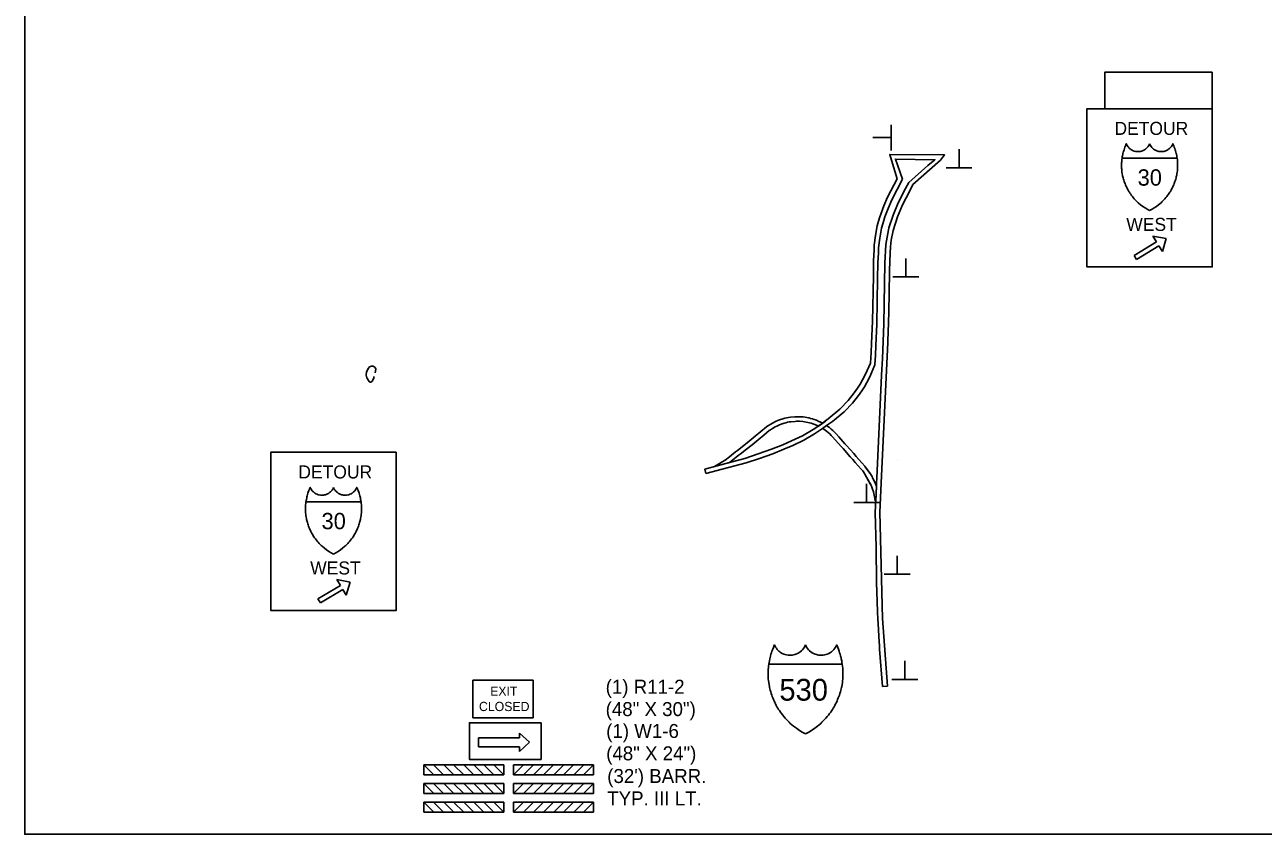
# Model space of a CAD drawing. Extents: x 759117 to 1215197, y 961017 to 2072683.
# Drawn here: x 759117 to 838885, y 961017 to 1013133 of the extents above; entities that cross this region are included whole.
import ezdxf

# ---------------------------------------------------------------- set-up
doc = ezdxf.new("R2010")
doc.units = 0
for name, color, linetype in [('23', 7, 'Continuous'), ('DETOUR', 7, 'Continuous'), ('G-ANNO-TEXT', 7, 'Continuous'), ('Level 19', 7, 'Continuous'), ('Level 3', 7, 'Continuous'), ('Level 35', 7, 'Continuous'), ('Level 8', 7, 'Continuous'), ('NO PLOT CELL', 7, 'Continuous')]:
    doc.layers.add(name, color=color, linetype=linetype)

msp = doc.modelspace()

# ---------------------------------------------------------------- linework, layer by layer
at = {"layer": '23'}
for points in [[(829792, 1004536), (829805, 1004620), (829819, 1004695), (829839, 1004792), (829853, 1004855), (829872, 1004930), (829897, 1005018), (829920, 1005091), (829945, 1005167), (829979, 1005260), (830014, 1005348), (830043, 1005415), (830067, 1005469), (830093, 1005411), (830123, 1005356), (830156, 1005306), (830199, 1005250), (830233, 1005212), (830276, 1005171), (830318, 1005136), (830365, 1005102), (830438, 1005058), (830514, 1005023), (830582, 1004999), (830650, 1004981), (830722, 1004969), (830806, 1004964), (830862, 1004965), (830925, 1004971), (830982, 1004980), (831042, 1004995), (831103, 1005015), (831186, 1005051), (831242, 1005083), (831308, 1005128), (831371, 1005181), (831417, 1005228), (831470, 1005292), (831513, 1005357), (831538, 1005402), (831566, 1005462)], [(831566, 1005462), (831594, 1005402), (831620, 1005357), (831663, 1005292), (831716, 1005228), (831762, 1005181), (831825, 1005128), (831891, 1005083), (831947, 1005051), (832029, 1005015), (832091, 1004995), (832151, 1004980), (832208, 1004971), (832271, 1004965), (832327, 1004964), (832411, 1004969), (832483, 1004981), (832551, 1004999), (832619, 1005023), (832695, 1005058), (832768, 1005102), (832815, 1005136), (832857, 1005171), (832900, 1005212), (832934, 1005250), (832977, 1005306), (833010, 1005356), (833040, 1005411), (833066, 1005469), (833090, 1005415), (833119, 1005348), (833154, 1005260), (833188, 1005167), (833213, 1005091), (833236, 1005018), (833261, 1004930), (833280, 1004855), (833294, 1004792), (833314, 1004695), (833328, 1004620), (833341, 1004536)], [(831566, 1001175), (831411, 1001257), (831274, 1001340), (831124, 1001441), (830983, 1001548), (830830, 1001679), (830772, 1001732), (830707, 1001796), (830647, 1001858), (830581, 1001931), (830516, 1002006), (830462, 1002073), (830403, 1002149), (830350, 1002223), (830303, 1002291), (830263, 1002353), (830229, 1002408), (830185, 1002483), (830150, 1002545), (830112, 1002618), (830075, 1002693), (830043, 1002762), (830014, 1002829), (829984, 1002904), (829957, 1002974), (829931, 1003047), (829907, 1003123), (829883, 1003200), (829863, 1003275), (829845, 1003345), (829831, 1003408), (829821, 1003455), (829804, 1003545), (829788, 1003649), (829777, 1003736), (829769, 1003828), (829764, 1003902), (829761, 1003996), (829760, 1004084), (829762, 1004181), (829765, 1004245), (829768, 1004304), (829771, 1004341), (829780, 1004437), (829792, 1004536)], [(833341, 1004536), (829792, 1004536)], [(829792, 1004536), (833341, 1004536)], [(833341, 1004536), (833353, 1004437), (833362, 1004341), (833365, 1004304), (833368, 1004245), (833371, 1004181), (833373, 1004084), (833372, 1003996), (833368, 1003902), (833364, 1003828), (833356, 1003736), (833345, 1003649), (833329, 1003545), (833312, 1003455), (833302, 1003408), (833288, 1003345), (833270, 1003275), (833250, 1003200), (833226, 1003123), (833201, 1003047), (833176, 1002974), (833149, 1002904), (833119, 1002829), (833090, 1002762), (833057, 1002693), (833020, 1002618), (832982, 1002545), (832948, 1002483), (832904, 1002408), (832870, 1002353), (832829, 1002291), (832783, 1002223), (832730, 1002149), (832671, 1002073), (832617, 1002006), (832552, 1001931), (832486, 1001858), (832426, 1001796), (832361, 1001732), (832303, 1001679), (832150, 1001548), (832009, 1001441), (831859, 1001340), (831722, 1001257), (831566, 1001175)], [(777229, 982416), (777242, 982501), (777255, 982576), (777275, 982672), (777290, 982735), (777309, 982810), (777333, 982898), (777356, 982972), (777381, 983047), (777415, 983141), (777450, 983228), (777479, 983296), (777503, 983349), (777529, 983292), (777560, 983237), (777593, 983186), (777636, 983130), (777670, 983093), (777712, 983052), (777755, 983016), (777801, 982982), (777875, 982938), (777950, 982903), (778019, 982879), (778086, 982861), (778159, 982849), (778243, 982844), (778298, 982845), (778362, 982851), (778418, 982861), (778479, 982875), (778540, 982896), (778622, 982932), (778679, 982964), (778745, 983009), (778808, 983062), (778854, 983108), (778906, 983172), (778950, 983237), (778975, 983282), (779003, 983342)], [(779003, 983342), (779031, 983282), (779056, 983237), (779100, 983172), (779152, 983108), (779198, 983062), (779262, 983009), (779327, 982964), (779384, 982932), (779466, 982896), (779527, 982875), (779588, 982861), (779644, 982851), (779708, 982845), (779763, 982844), (779847, 982849), (779920, 982861), (779987, 982879), (780056, 982903), (780131, 982938), (780205, 982982), (780251, 983016), (780294, 983052), (780336, 983093), (780370, 983130), (780413, 983186), (780447, 983237), (780477, 983292), (780503, 983349), (780527, 983296), (780556, 983228), (780591, 983141), (780625, 983047), (780650, 982972), (780673, 982898), (780697, 982810), (780716, 982735), (780731, 982672), (780751, 982576), (780764, 982501), (780777, 982416)], [(779003, 979055), (778848, 979138), (778711, 979220), (778560, 979322), (778420, 979428), (778266, 979559), (778209, 979612), (778144, 979676), (778083, 979738), (778017, 979811), (777952, 979886), (777898, 979953), (777840, 980030), (777786, 980103), (777740, 980171), (777699, 980234), (777666, 980288), (777621, 980364), (777587, 980426), (777549, 980498), (777512, 980573), (777480, 980643), (777451, 980710), (777420, 980785), (777394, 980854), (777368, 980927), (777343, 981003), (777320, 981081), (777300, 981155), (777282, 981225), (777268, 981288), (777258, 981335), (777241, 981425), (777225, 981530), (777214, 981616), (777206, 981708), (777201, 981782), (777198, 981876), (777197, 981964), (777198, 982062), (777201, 982126), (777205, 982185), (777207, 982222), (777217, 982318), (777229, 982416)], [(780777, 982416), (777229, 982416)], [(777229, 982416), (780777, 982416)], [(780777, 982416), (780789, 982318), (780799, 982222), (780801, 982185), (780805, 982126), (780808, 982062), (780809, 981964), (780809, 981876), (780805, 981782), (780800, 981708), (780792, 981616), (780781, 981530), (780765, 981425), (780748, 981335), (780738, 981288), (780724, 981225), (780707, 981155), (780686, 981081), (780663, 981003), (780638, 980927), (780612, 980854), (780586, 980785), (780555, 980710), (780526, 980643), (780494, 980573), (780457, 980498), (780419, 980426), (780385, 980364), (780340, 980288), (780307, 980234), (780266, 980171), (780220, 980103), (780166, 980030), (780108, 979953), (780054, 979886), (779989, 979811), (779923, 979738), (779862, 979676), (779797, 979612), (779740, 979559), (779586, 979428), (779446, 979322), (779295, 979220), (779158, 979138), (779003, 979055)], [(807040, 971965), (807058, 972078), (807075, 972178), (807102, 972307), (807121, 972391), (807147, 972491), (807180, 972608), (807210, 972706), (807244, 972807), (807289, 972931), (807335, 973048), (807374, 973138), (807406, 973210), (807441, 973133), (807481, 973059), (807525, 972992), (807583, 972918), (807628, 972868), (807685, 972813), (807742, 972765), (807803, 972720), (807901, 972662), (808002, 972615), (808093, 972582), (808183, 972559), (808280, 972543), (808392, 972536), (808466, 972537), (808551, 972545), (808626, 972558), (808707, 972578), (808788, 972605), (808898, 972653), (808973, 972695), (809061, 972755), (809145, 972826), (809207, 972888), (809277, 972973), (809335, 973060), (809369, 973121), (809406, 973201)], [(809406, 973201), (809443, 973121), (809477, 973060), (809535, 972973), (809605, 972888), (809666, 972826), (809751, 972755), (809838, 972695), (809914, 972653), (810023, 972605), (810105, 972578), (810185, 972558), (810261, 972545), (810346, 972537), (810419, 972536), (810532, 972543), (810628, 972559), (810718, 972582), (810809, 972615), (810910, 972662), (811008, 972720), (811070, 972765), (811127, 972813), (811183, 972868), (811229, 972918), (811286, 972992), (811330, 973059), (811371, 973133), (811406, 973210), (811438, 973138), (811476, 973048), (811523, 972931), (811568, 972807), (811602, 972706), (811632, 972608), (811665, 972491), (811690, 972391), (811710, 972307), (811736, 972178), (811754, 972078), (811771, 971965)], [(809406, 967484), (809199, 967594), (809016, 967704), (808816, 967840), (808628, 967981), (808424, 968156), (808347, 968227), (808260, 968312), (808180, 968395), (808092, 968492), (808005, 968592), (807933, 968681), (807855, 968783), (807783, 968882), (807722, 968972), (807668, 969056), (807623, 969128), (807564, 969229), (807518, 969312), (807467, 969408), (807418, 969508), (807375, 969601), (807336, 969690), (807295, 969790), (807260, 969883), (807226, 969980), (807193, 970081), (807162, 970185), (807134, 970284), (807111, 970378), (807092, 970462), (807079, 970524), (807056, 970644), (807035, 970784), (807020, 970899), (807009, 971021), (807003, 971120), (806999, 971246), (806997, 971363), (807000, 971493), (807003, 971578), (807008, 971657), (807012, 971706), (807024, 971834), (807040, 971965)], [(811771, 971965), (807040, 971965)], [(807040, 971965), (811771, 971965)], [(811771, 971965), (811788, 971834), (811800, 971706), (811804, 971657), (811808, 971578), (811812, 971493), (811814, 971363), (811813, 971246), (811808, 971120), (811802, 971021), (811792, 970899), (811777, 970784), (811755, 970644), (811733, 970524), (811720, 970462), (811701, 970378), (811677, 970284), (811650, 970185), (811619, 970081), (811586, 969980), (811552, 969883), (811516, 969790), (811475, 969690), (811437, 969601), (811394, 969508), (811345, 969408), (811294, 969312), (811248, 969229), (811189, 969128), (811144, 969056), (811090, 968972), (811028, 968882), (810957, 968783), (810879, 968681), (810807, 968592), (810720, 968492), (810632, 968395), (810551, 968312), (810465, 968227), (810388, 968156), (810183, 967981), (809996, 967840), (809795, 967704), (809613, 967594), (809406, 967484)]]:
    msp.add_lwpolyline(points, dxfattribs=at)
at = {"layer": 'DETOUR'}
for p, q in [((814928, 1005035), (814928, 1006698)), ((814928, 1005866), (813731, 1005866)), ((819293, 1003919), (819293, 1005116)), ((818090, 1004417), (816323, 1002843)), ((816323, 1002843), (818090, 1004417)), ((818461, 1003919), (820124, 1003919)), ((832011, 999160), (830565, 998284)), ((832167, 998903), (830720, 998028)), ((815867, 996896), (815867, 998093)), ((830565, 998284), (830720, 998028)), ((815035, 996896), (816698, 996896)), ((802911, 984531), (802987, 984243)), ((802911, 984531), (802987, 984243)), ((813343, 982375), (813343, 983573)), ((812511, 982375), (814174, 982375)), ((815307, 977752), (815307, 978949)), ((814476, 977752), (816139, 977752)), ((779448, 977040), (778001, 976165)), ((779603, 976784), (778157, 975908)), ((778001, 976165), (778157, 975908)), ((815798, 970984), (815798, 972181)), ((814966, 970984), (816629, 970984)), ((814369, 970526), (814690, 970556)), ((814369, 970526), (814690, 970556))]:
    msp.add_line(p, q, dxfattribs=at)
for points in [[(818090, 1004417), (818361, 1004756), (814825, 1004788), (814949, 1004413), (815312, 1003208)], [(818090, 1004417), (818361, 1004756), (814825, 1004788), (814949, 1004413), (815312, 1003208)], [(817288, 1004068), (817738, 1004441), (815197, 1004489), (815657, 1003193)], [(815657, 1003193), (815197, 1004489), (817738, 1004441), (817288, 1004068)], [(813897, 981735), (813974, 983412), (813984, 983643), (813999, 983951), (814304, 990583), (814353, 991642), (814447, 993849), (814514, 997780), (814585, 998978), (814752, 999937), (814778, 1000054), (815044, 1000878), (815382, 1001668), (815854, 1002588), (816060, 1002981), (817288, 1004068)], [(817288, 1004068), (816060, 1002981), (815854, 1002588), (815382, 1001668), (815044, 1000878), (814778, 1000054), (814752, 999937), (814585, 998978), (814514, 997780), (814447, 993849), (814353, 991642), (814304, 990583), (813999, 983951), (813984, 983643), (813974, 983412), (813897, 981735)], [(815312, 1003208), (814694, 1002030), (814446, 1001467), (814245, 1000944), (814166, 1000703), (814029, 1000196), (813906, 999555), (813833, 998947), (813820, 998625), (813782, 997961), (813774, 996951), (813715, 994026), (813658, 992643), (813630, 992034), (813586, 991344), (813269, 990642), (813080, 990269), (812918, 989985), (812757, 989732), (812545, 989426), (812152, 988941), (811988, 988760), (811813, 988580), (811613, 988384), (810862, 987760), (810489, 987489)], [(815312, 1003208), (814694, 1002030), (814446, 1001467), (814245, 1000944), (814166, 1000703), (814029, 1000196), (813906, 999555), (813833, 998947), (813820, 998625), (813782, 997961), (813774, 996951), (813715, 994026), (813658, 992643), (813630, 992034), (813586, 991344), (813269, 990642), (813080, 990269), (812918, 989985), (812757, 989732), (812545, 989426), (812152, 988941), (811988, 988760), (811813, 988580), (811613, 988384), (810862, 987760), (810678, 987627)], [(815657, 1003193), (814971, 1001864), (814723, 1001301), (814523, 1000778), (814443, 1000537), (814306, 1000030), (814184, 999389), (814111, 998781), (814097, 998459), (814060, 997795), (814051, 996785), (813993, 993860), (813936, 992477), (813908, 991867), (813878, 991229), (813546, 990476), (813358, 990103), (813195, 989819), (813034, 989566), (812822, 989260), (812429, 988775), (812265, 988594), (812091, 988414), (811891, 988218), (811139, 987594), (810766, 987323)], [(810766, 987323), (811139, 987594), (811891, 988218), (812091, 988414), (812265, 988594), (812429, 988775), (812822, 989260), (813034, 989566), (813195, 989819), (813358, 990103), (813546, 990476), (813878, 991229), (813908, 991867), (813936, 992477), (813993, 993860), (814051, 996785), (814060, 997795), (814097, 998459), (814111, 998781), (814184, 999389), (814306, 1000030), (814443, 1000537), (814523, 1000778), (814723, 1001301), (814971, 1001864), (815657, 1003193)], [(816323, 1002843), (816119, 1002451), (815651, 1001540), (815322, 1000772), (815043, 999877), (814927, 999273), (814869, 998834), (814849, 998422), (814806, 997331), (814783, 995757), (814764, 994771), (814745, 993841), (814734, 993460), (814698, 992684), (814677, 992230), (814302, 984091), (814194, 981742)], [(814194, 981742), (814302, 984091), (814677, 992230), (814698, 992684), (814734, 993460), (814745, 993841), (814764, 994771), (814783, 995757), (814806, 997331), (814849, 998422), (814869, 998834), (814927, 999273), (815043, 999877), (815322, 1000772), (815651, 1001540), (816119, 1002451), (816323, 1002843)], [(810690, 987610), (810431, 987422), (809906, 987074), (809217, 986668), (808504, 986343), (807939, 986088), (807212, 985802), (806364, 985498), (805501, 985211), (803958, 984808), (802911, 984531)], [(810606, 987574), (810489, 987489), (810229, 987288)], [(810678, 987627), (810606, 987574)], [(810229, 987288), (809906, 987074), (809217, 986668), (808504, 986343), (807939, 986088), (807212, 985802), (806364, 985498), (805501, 985211), (803958, 984808), (802911, 984531)], [(810766, 987323), (810507, 987134), (809982, 986786), (809293, 986380), (808580, 986055), (808015, 985800), (807289, 985515), (806440, 985210), (805577, 984923), (804034, 984521), (802987, 984243)], [(802987, 984243), (804034, 984521), (805577, 984923), (806440, 985210), (807289, 985515), (808015, 985800), (808580, 986055), (809293, 986380), (809982, 986786), (810507, 987134), (810766, 987323)], [(814369, 970526), (814176, 972939), (814161, 973153), (814130, 973726), (814109, 974221), (814068, 974890), (814047, 975305), (814027, 976017), (813977, 977197), (813950, 979491), (813897, 981735)], [(813897, 981735), (813950, 979491), (813977, 977197), (814027, 976017), (814047, 975305), (814068, 974890), (814109, 974221), (814130, 973726), (814161, 973153), (814176, 972939), (814369, 970526)], [(814194, 981742), (814365, 974907), (814690, 970556)], [(814690, 970556), (814365, 974907), (814194, 981742)]]:
    msp.add_lwpolyline(points, dxfattribs=at)
at = {"layer": 'Level 19'}
for p, q in [((810435, 987519), (810270, 987599)), ((810146, 987328), (810229, 987288)), ((810229, 987288), (810431, 987422)), ((810431, 987422), (810500, 987472)), ((810505, 987480), (810435, 987519)), ((810766, 987323), (810507, 987134)), ((813248, 984676), (813218, 984712)), ((813248, 984676), (813587, 984216)), ((813234, 984209), (813614, 983507)), ((813234, 984209), (813577, 983575)), ((813723, 983971), (813904, 983587)), ((813974, 983412), (813904, 983587)), ((813931, 982480), (813974, 983412))]:
    msp.add_line(p, q, dxfattribs=at)
for points in [[(810270, 987599), (810108, 987669), (809966, 987722), (809851, 987759), (809734, 987792), (809617, 987821), (809498, 987846), (809379, 987866), (809258, 987881), (809033, 987899), (808925, 987901), (808818, 987900), (808711, 987896), (808432, 987871), (808309, 987852), (808189, 987828), (808070, 987800), (807951, 987767), (807731, 987693), (807625, 987651), (807521, 987607), (807419, 987558), (807319, 987506), (807138, 987405), (807053, 987353), (806975, 987302), (806887, 987238), (806524, 986941), (806160, 986637), (805773, 986318), (805424, 986035), (805016, 985720), (804889, 985629), (804508, 985325), (804233, 985110), (804084, 985009), (803541, 984698)], [(804502, 984950), (804692, 985092), (805068, 985392), (805193, 985481), (805609, 985801), (805962, 986088), (806350, 986408), (806713, 986712), (807069, 987002), (807145, 987057), (807213, 987102), (807288, 987148), (807460, 987244), (807551, 987292), (807644, 987335), (807738, 987376), (807833, 987413), (808038, 987482), (808144, 987512), (808252, 987537), (808360, 987559), (808468, 987575), (808730, 987599), (808826, 987603), (808923, 987604), (809018, 987602), (809227, 987585), (809335, 987571), (809443, 987553), (809551, 987531), (809658, 987505), (809764, 987475), (809868, 987441), (809997, 987393), (810146, 987328)], [(810500, 987472), (810505, 987480)], [(810507, 987134), (810584, 987087), (810674, 987026), (810761, 986963), (810862, 986878), (810962, 986787), (811058, 986695), (811153, 986599), (811322, 986407)], [(811544, 986605), (811371, 986802), (811267, 986907), (811165, 987005), (811057, 987102), (810945, 987197), (810845, 987269), (810766, 987323)], [(811322, 986407), (811727, 985956), (811829, 985845), (812286, 985321), (812454, 985136), (812612, 984951), (812993, 984516)], [(813218, 984712), (812837, 985146), (812677, 985333), (812508, 985519), (812051, 986045), (811946, 986156), (811544, 986605)], [(803541, 984698), (803958, 984808), (804502, 984950)], [(804502, 984950), (804502, 984950)], [(812993, 984516), (813086, 984409), (813130, 984354), (813212, 984242)], [(813587, 984216), (813555, 984260), (813248, 984676)], [(813212, 984242), (813234, 984209)], [(813577, 983575), (813582, 983578)], [(813582, 983578), (813614, 983507), (813646, 983437)], [(813723, 983971), (813689, 984040), (813616, 984169), (813587, 984216)], [(813904, 983587), (813888, 983623), (813756, 983902), (813723, 983971)], [(813646, 983437), (813723, 983234), (813781, 983054), (813833, 982850), (813858, 982731), (813897, 982482)], [(813897, 982482), (813931, 982480)]]:
    msp.add_lwpolyline(points, dxfattribs=at)
at = {"layer": 'Level 3'}
for p, q in [((815349, 985063), (815346, 985066)), ((787978, 968507), (787978, 970939)), ((787978, 970939), (791870, 970939)), ((791870, 968507), (791870, 970939)), ((787978, 968507), (791870, 968507)), ((788349, 966641), (788349, 967228)), ((789980, 965490), (784817, 965490)), ((784817, 964842), (784817, 965490)), ((789980, 964844), (789980, 965490)), ((790590, 964844), (790590, 965490)), ((790590, 965490), (795753, 965490)), ((795753, 964842), (795753, 965490)), ((789980, 964830), (784817, 964830)), ((790590, 964830), (795753, 964830)), ((789980, 964288), (784817, 964288)), ((784817, 963642), (784817, 964288)), ((789980, 963642), (784817, 963642)), ((789980, 963642), (789980, 964288)), ((790590, 964288), (795753, 964288)), ((790590, 963642), (790590, 964288)), ((790590, 963642), (795753, 963642)), ((795753, 963642), (795753, 964288)), ((784817, 962444), (784817, 963091)), ((789980, 963091), (784817, 963091)), ((789980, 962444), (789980, 963091)), ((790590, 963091), (795753, 963091)), ((790590, 962444), (790590, 963091)), ((795753, 962444), (795753, 963091)), ((789980, 962431), (784817, 962431)), ((790590, 962431), (795753, 962431))]:
    msp.add_line(p, q, dxfattribs=at)
for points in [[(784817, 965490), (785452, 965488), (786097, 964844), (785464, 964844)], [(786107, 965490), (786742, 965488), (787387, 964844), (786754, 964844)], [(787397, 965490), (788032, 965488), (788677, 964844), (788044, 964844)], [(788687, 965490), (789322, 965488), (789967, 964844), (789334, 964844)], [(791883, 965490), (791248, 965488), (790604, 964844), (791237, 964844)], [(793173, 965490), (792538, 965488), (791894, 964844), (792527, 964844)], [(794463, 965490), (793828, 965488), (793184, 964844), (793817, 964844)], [(795753, 965490), (795118, 965488), (794474, 964844), (795107, 964844)], [(784817, 964288), (785452, 964286), (786097, 963642), (785464, 963642)], [(786107, 964288), (786742, 964286), (787387, 963642), (786754, 963642)], [(787397, 964288), (788032, 964286), (788677, 963642), (788044, 963642)], [(788687, 964288), (789322, 964286), (789967, 963642), (789334, 963642)], [(791883, 964288), (791248, 964286), (790604, 963642), (791237, 963642)], [(793173, 964288), (792538, 964286), (791894, 963642), (792527, 963642)], [(794463, 964288), (793828, 964286), (793184, 963642), (793817, 963642)], [(795753, 964288), (795118, 964286), (794474, 963642), (795107, 963642)], [(784817, 963091), (785452, 963089), (786097, 962444), (785464, 962444)], [(786107, 963091), (786742, 963089), (787387, 962444), (786754, 962444)], [(787397, 963091), (788032, 963089), (788677, 962444), (788044, 962444)], [(788687, 963091), (789322, 963089), (789967, 962444), (789334, 962444)], [(791883, 963091), (791248, 963089), (790604, 962444), (791237, 962444)], [(793173, 963091), (792538, 963089), (791894, 962444), (792527, 962444)], [(794463, 963091), (793828, 963089), (793184, 962444), (793817, 962444)], [(795753, 963091), (795118, 963089), (794474, 962444), (795107, 962444)]]:
    msp.add_lwpolyline(points, close=True, dxfattribs=at)
at = {"layer": 'Level 35'}
msp.add_lwpolyline([(781685, 990714), (781719, 990960), (781696, 991062), (781625, 991120), (781558, 991147), (781460, 991152), (781376, 991136), (781324, 991107), (781252, 991028), (781138, 990780), (781114, 990569), (781141, 990394), (781289, 990155), (781356, 990125), (781402, 990126), (781488, 990183), (781580, 990336), (781619, 990491)], dxfattribs=at)
at = {"layer": 'Level 8'}
for p, q in [((831785, 999533), (832639, 999365)), ((831785, 999533), (832011, 999160)), ((832167, 998903), (832392, 998530)), ((832639, 999365), (832392, 998530)), ((779222, 977414), (780075, 977245)), ((779222, 977414), (779448, 977040)), ((780075, 977245), (779829, 976410)), ((779603, 976784), (779829, 976410)), ((788349, 967228), (790982, 967228)), ((790982, 967521), (791625, 966935)), ((790982, 967521), (790982, 967228)), ((791625, 966935), (790982, 966348)), ((788349, 966641), (790982, 966641)), ((790982, 966641), (790982, 966348))]:
    msp.add_line(p, q, dxfattribs=at)
for points in [[(835606, 1010092), (828686, 1010092), (828686, 1007731), (835606, 1007731)], [(835606, 1007731), (835606, 997548), (827527, 997548), (827527, 1007731)], [(783043, 985611), (783043, 975428), (774963, 975428), (774963, 985611)], [(792377, 968192), (787761, 968192), (787761, 965831), (792377, 965831)]]:
    msp.add_lwpolyline(points, close=True, dxfattribs=at)
at = {"layer": 'NO PLOT CELL'}
msp.add_lwpolyline([(875318, 1065249), (875318, 1050499), (888818, 1050499), (888818, 1060294), (918653, 1060294), (918653, 1045544), (918653, 961017), (759117, 961017), (759117, 1065249)], close=True, dxfattribs=at)

# ---------------------------------------------------------------- texts
at = {"layer": 'G-ANNO-TEXT'}
for s, height, p in [('30', 1051.6, (830795, 1002774)), ('30', 1051.6, (778232, 980654)), ('530', 1402.1, (807721, 969617))]:
    msp.add_text(s, height=height, dxfattribs=at).set_placement(p)
at = {"layer": 'Level 3'}
for s, height, p in [('EXIT', 589.2, (789093, 969933)), ('CLOSED', 592.1, (788371, 968946))]:
    msp.add_text(s, height=height, dxfattribs=at).set_placement(p)
at = {"layer": 'Level 8'}
for s, height, p in [('DETOUR', 841.8, (829303, 1006042)), ('WEST', 841.8, (830065, 999860)), ('DETOUR', 841.8, (776739, 983922)), ('WEST', 841.8, (777502, 977740)), ('(1) R11-2', 900.3, (796532, 970064)), ('(48" X 30")', 900.31, (796532, 968623)), ('(1) W1-6', 900.3, (796566, 967214)), ('(48" X 24")', 900.31, (796566, 965774)), ("(32') BARR.", 900.31, (796633, 964314)), ('TYP. III LT.', 900.31, (796633, 962873))]:
    msp.add_text(s, height=height, dxfattribs=at).set_placement(p)

doc.saveas('drawing.dxf')
